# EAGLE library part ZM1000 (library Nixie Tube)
Indicator Tube (numeral height 14mm, no filter, side view, long-life typ)
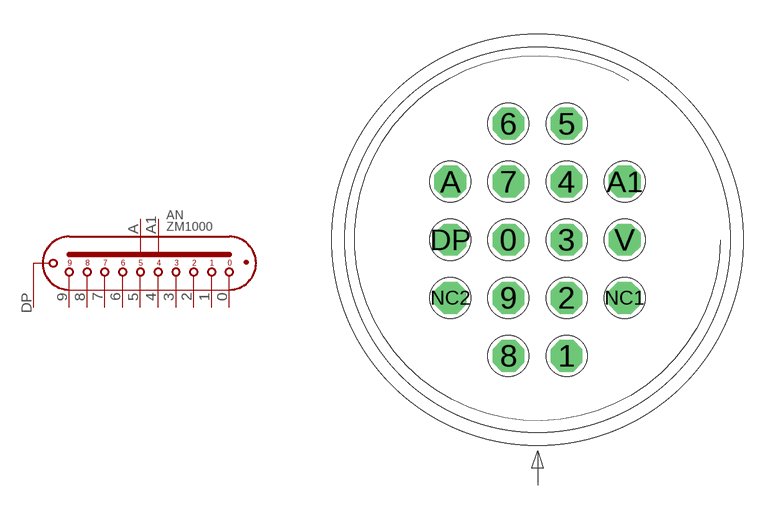
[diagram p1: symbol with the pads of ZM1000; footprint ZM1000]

Designator prefix AN

## ZM1000  [ZM1000]
0  0  pas
1  1  pas
2  2  pas
3  3  pas
4  4  pas
5  5  pas
6  6  pas
7  7  pas
8  8  pas
9  9  pas
A  A1  pas
A1  A2  pas
DP  DPL  pas

## Footprint ZM1000 (pad centres in mm)
Direct print
drill 0.813 pad 1.397 octagon: 0 -1.27,0; 1 1.27,-5.08; 2 1.27,-2.54; 3 1.27,0; 4 1.27,2.54; 5 1.27,5.08; 6 -1.27,5.08; 7 -1.27,2.54; 8 -1.27,-5.08; 9 -1.27,-2.54; A -3.81,2.54; A1 3.81,2.54; DP -3.81,0; NC1 3.81,-2.54; NC2 -3.81,-2.54; V 3.81,0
